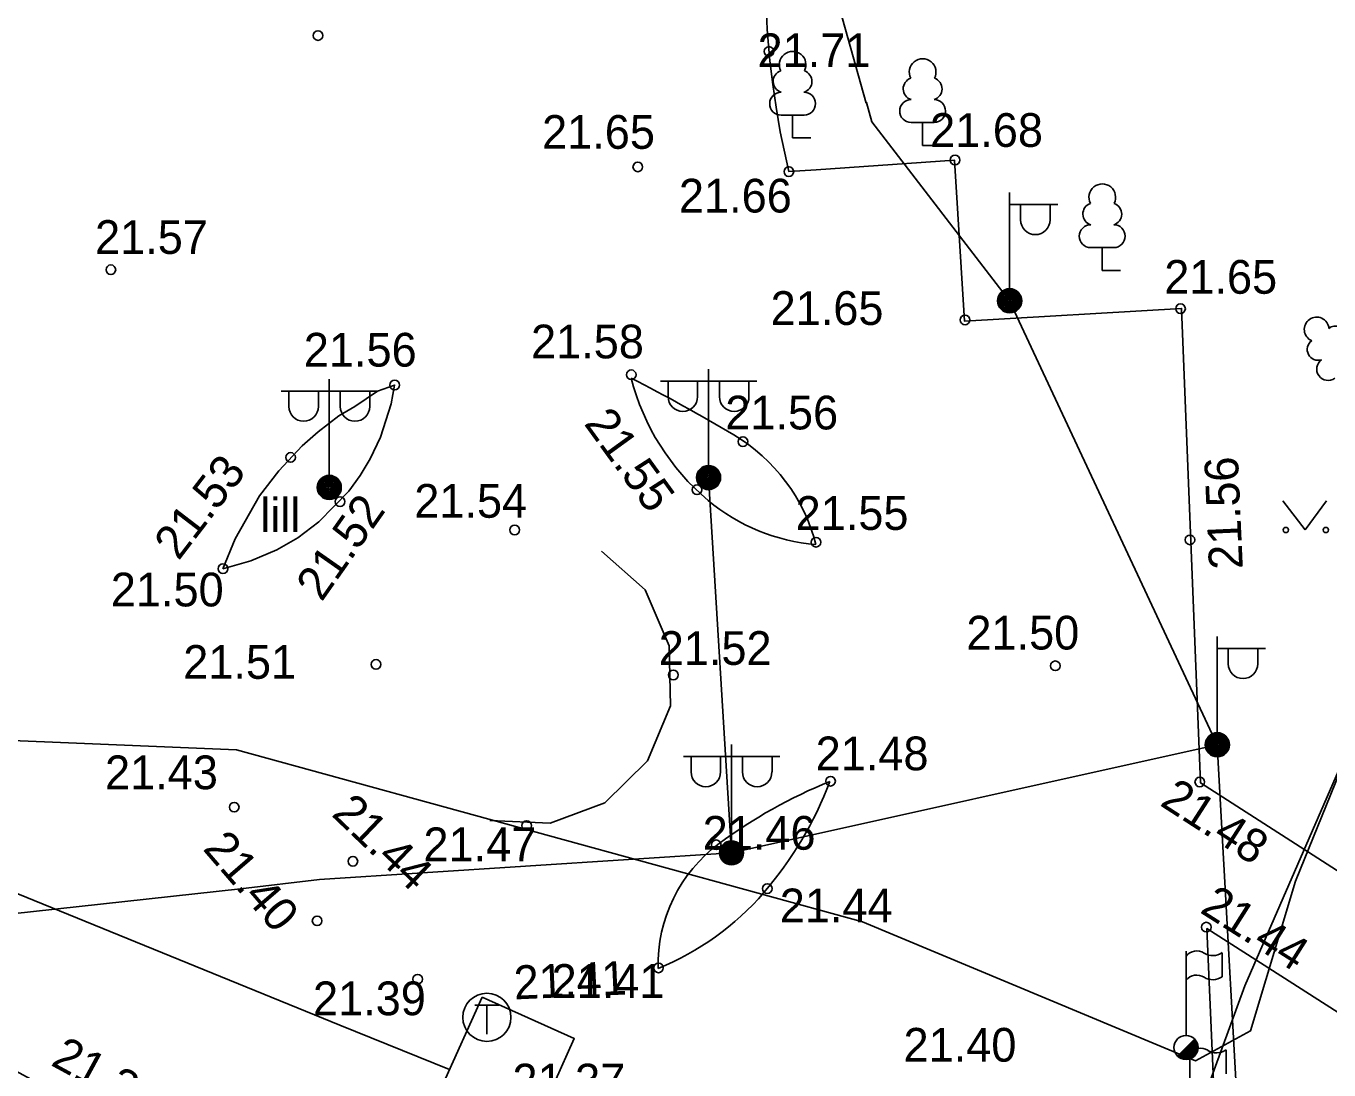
# Model space of a CAD drawing. Extents: x 714038 to 714279, y 6589845 to 6590041.
# Drawn here: x 714222.12 to 714249.16, y 6589934.18 to 6589955.84 of the extents above; entities that cross this region are included whole.
import ezdxf

# ---------------------------------------------------------------- set-up
doc = ezdxf.new("R2010")
doc.units = 0
for name, color, linetype in [('HALJASTUS', 7, 'Continuous'), ('KORGUS', 7, 'Continuous'), ('KPKAABEL', 7, 'Continuous'), ('MPKAABEL', 7, 'Continuous'), ('POST', 7, 'Continuous'), ('PUU', 7, 'Continuous'), ('RAJATIS', 7, 'Continuous'), ('TEE', 7, 'Continuous'), ('TKAEV', 7, 'Continuous'), ('TTRASS', 7, 'Continuous'), ('VTRASS', 7, 'Continuous')]:
    doc.layers.add(name, color=color, linetype=linetype)

msp = doc.modelspace()

# ---------------------------------------------------------------- linework, layer by layer
at = {"layer": 'HALJASTUS'}
for p, q in [((714248.205, 6589945.991), (714248.668, 6589945.384)), ((714248.668, 6589945.384), (714249.114, 6589945.991))]:
    msp.add_line(p, q, dxfattribs=at)
for centre in [(714248.267, 6589945.384), (714249.096, 6589945.384)]:
    msp.add_circle(centre, 0.055, dxfattribs=at)
at = {"layer": 'KORGUS'}
for centre in [(714228.182, 6589955.646), (714237.541, 6589955.316), (714241.402, 6589953.063), (714234.818, 6589952.92), (714237.953, 6589952.822), (714223.882, 6589950.785), (714246.081, 6589949.977), (714241.609, 6589949.744), (714234.682, 6589948.606), (714229.772, 6589948.392), (714236.999, 6589947.218), (714227.612, 6589946.89), (714236.047, 6589946.219), (714228.639, 6589945.973), (714232.264, 6589945.384), (714246.276, 6589945.179), (714238.517, 6589945.13), (714226.209, 6589944.581), (714229.385, 6589942.594), (714243.482, 6589942.565), (714235.554, 6589942.375), (714238.818, 6589940.17), (714246.481, 6589940.154), (714226.442, 6589939.631), (714232.51, 6589939.249), (714236.445, 6589938.85), (714228.905, 6589938.508), (714237.504, 6589937.941), (714228.163, 6589937.272), (714246.616, 6589937.141), (714235.247, 6589936.296), (714230.248, 6589936.061)]:
    msp.add_circle(centre, 0.1, dxfattribs=at)
at = {"layer": 'KPKAABEL'}
msp.add_lwpolyline([(714278.95, 6590013.083), (714274.696, 6590002.154), (714268.806, 6589986.746), (714264.689, 6589977.209), (714260.118, 6589965.851), (714258.032, 6589961.24), (714253.05, 6589949.372), (714248.466, 6589938.096), (714247.531, 6589934.989), (714246.389, 6589934.367), (714239.483, 6589937.254), (714226.492, 6589940.819), (714222.669, 6589940.979), (714220.982, 6589941.049), (714220.257, 6589940.365), (714218.76, 6589936.611), (714215.836, 6589929.757), (714212.225, 6589922.206), (714208.098, 6589916.26), (714202.344, 6589907.69)], dxfattribs=at)
at = {"layer": 'MPKAABEL'}
for points in [[(714167.029, 6589999.261), (714167.805, 6589985.535), (714167.801, 6589985.524), (714168.701, 6589969.69), (714168.856, 6589964.517), (714181.003, 6589963.765), (714182.873, 6589963.649), (714187.834, 6589963.342), (714201.122, 6589963.986), (714214.138, 6589964.636), (714217.634, 6589964.759), (714217.843, 6589958.743), (714218.335, 6589947.958), (714218.782, 6589937.076), (714219.871, 6589937.206), (714226.57, 6589937.936), (714228.214, 6589938.132), (714236.763, 6589938.683), (714246.845, 6589940.926), (714247.938, 6589921.303)], [(714246.845, 6589940.926), (714242.535, 6589950.141), (714239.677, 6589953.853), (714239.565, 6589954.253), (714239.558, 6589954.244), (714238.036, 6589959.673), (714239.482, 6589959.737), (714240.828, 6589959.797), (714241.687, 6589959.835), (714251.347, 6589960.263), (714264.335, 6589960.615)], [(714236.763, 6589938.683), (714236.286, 6589946.472)]]:
    msp.add_lwpolyline(points, dxfattribs=at)
at = {"layer": 'POST'}
for p, q in [((714242.535, 6589950.391), (714242.535, 6589952.391)), ((714242.535, 6589952.141), (714243.535, 6589952.141)), ((714242.761, 6589951.82), (714242.761, 6589952.141)), ((714243.374, 6589951.82), (714243.374, 6589952.141)), ((714228.415, 6589946.517), (714228.415, 6589948.517)), ((714236.286, 6589946.722), (714236.286, 6589948.722)), ((714228.415, 6589948.267), (714227.415, 6589948.267)), ((714227.576, 6589947.946), (714227.576, 6589948.267)), ((714228.188, 6589947.946), (714228.188, 6589948.267)), ((714228.415, 6589948.267), (714229.415, 6589948.267)), ((714228.642, 6589947.946), (714228.642, 6589948.267)), ((714229.254, 6589947.946), (714229.254, 6589948.267)), ((714236.286, 6589948.472), (714235.286, 6589948.472)), ((714235.446, 6589948.151), (714235.446, 6589948.472)), ((714236.059, 6589948.151), (714236.059, 6589948.472)), ((714236.286, 6589948.472), (714237.286, 6589948.472)), ((714236.512, 6589948.151), (714236.512, 6589948.472)), ((714237.125, 6589948.151), (714237.125, 6589948.472)), ((714246.845, 6589941.176), (714246.845, 6589943.176)), ((714246.845, 6589942.926), (714247.845, 6589942.926)), ((714247.072, 6589942.605), (714247.072, 6589942.926)), ((714247.684, 6589942.605), (714247.684, 6589942.926)), ((714236.763, 6589940.683), (714235.763, 6589940.683)), ((714235.924, 6589940.362), (714235.924, 6589940.683)), ((714236.537, 6589940.362), (714236.537, 6589940.683)), ((714236.763, 6589938.933), (714236.763, 6589940.933)), ((714236.763, 6589940.683), (714237.763, 6589940.683)), ((714236.99, 6589940.362), (714236.99, 6589940.683)), ((714237.603, 6589940.362), (714237.603, 6589940.683)), ((714246.017, 6589934.466), (714246.371, 6589934.819))]:
    msp.add_line(p, q, dxfattribs=at)
for centre, radius in [((714242.535, 6589950.141), 0.25), ((714242.535, 6589950.141), 0.225), ((714242.535, 6589950.141), 0.2), ((714242.535, 6589950.141), 0.175), ((714242.535, 6589950.141), 0.15), ((714242.535, 6589950.141), 0.125), ((714242.535, 6589950.141), 0.1), ((714242.535, 6589950.141), 0.075), ((714242.535, 6589950.141), 0.05), ((714242.535, 6589950.141), 0.025), ((714236.286, 6589946.472), 0.25), ((714236.286, 6589946.472), 0.225), ((714236.286, 6589946.472), 0.2), ((714236.286, 6589946.472), 0.175), ((714236.286, 6589946.472), 0.15), ((714228.415, 6589946.267), 0.25), ((714228.415, 6589946.267), 0.225), ((714228.415, 6589946.267), 0.2), ((714228.415, 6589946.267), 0.175), ((714228.415, 6589946.267), 0.15), ((714228.415, 6589946.267), 0.125), ((714228.415, 6589946.267), 0.1), ((714236.286, 6589946.472), 0.125), ((714236.286, 6589946.472), 0.1), ((714236.286, 6589946.472), 0.075), ((714236.286, 6589946.472), 0.05), ((714236.286, 6589946.472), 0.025), ((714228.415, 6589946.267), 0.075), ((714228.415, 6589946.267), 0.05), ((714228.415, 6589946.267), 0.025), ((714246.845, 6589940.926), 0.25), ((714246.845, 6589940.926), 0.225), ((714246.845, 6589940.926), 0.2), ((714246.845, 6589940.926), 0.175), ((714246.845, 6589940.926), 0.15), ((714246.845, 6589940.926), 0.125), ((714246.845, 6589940.926), 0.1), ((714246.845, 6589940.926), 0.075), ((714246.845, 6589940.926), 0.05), ((714246.845, 6589940.926), 0.025), ((714236.763, 6589938.683), 0.25), ((714236.763, 6589938.683), 0.225), ((714236.763, 6589938.683), 0.2), ((714236.763, 6589938.683), 0.175), ((714236.763, 6589938.683), 0.15), ((714236.763, 6589938.683), 0.125), ((714236.763, 6589938.683), 0.1), ((714236.763, 6589938.683), 0.075), ((714236.763, 6589938.683), 0.05), ((714236.763, 6589938.683), 0.025), ((714246.195, 6589934.643), 0.25)]:
    msp.add_circle(centre, radius, dxfattribs=at)
for centre, radius, start, end in [((714243.068, 6589951.82), 0.306, 180, 0), ((714235.753, 6589948.151), 0.306, 180, 0), ((714236.819, 6589948.151), 0.306, 180, 0), ((714227.882, 6589947.946), 0.306, 180, 0), ((714228.948, 6589947.946), 0.306, 180, 0), ((714247.378, 6589942.605), 0.306, 180, 0), ((714236.23, 6589940.362), 0.306, 180, 0), ((714237.296, 6589940.362), 0.306, 180, 0), ((714246.195, 6589934.643), 0.225, 224.8541, 45.0356), ((714246.195, 6589934.643), 0.2, 224.8427, 45.047), ((714246.195, 6589934.643), 0.175, 224.8281, 45.0616), ((714246.195, 6589934.643), 0.15, 224.8087, 45.081), ((714246.195, 6589934.643), 0.125, 224.7814, 45.1083), ((714246.195, 6589934.643), 0.1, 224.7406, 45.1491), ((714246.195, 6589934.643), 0.075, 224.6725, 45.2172), ((714246.195, 6589934.643), 0.05, 224.5363, 45.3534), ((714246.195, 6589934.643), 0.025, 224.1278, 45.7619)]:
    msp.add_arc(centre, radius, start, end, dxfattribs=at)
at = {"layer": 'PUU'}
for p, q in [((714238.27, 6589953.995), (714237.79, 6589953.995)), ((714238.03, 6589953.52), (714238.03, 6589953.995)), ((714240.969, 6589953.842), (714240.489, 6589953.842)), ((714240.729, 6589953.367), (714240.729, 6589953.842)), ((714238.41, 6589953.52), (714238.03, 6589953.52)), ((714241.109, 6589953.367), (714240.729, 6589953.367)), ((714244.697, 6589951.244), (714244.217, 6589951.244)), ((714244.457, 6589950.769), (714244.457, 6589951.244)), ((714244.837, 6589950.769), (714244.457, 6589950.769))]:
    msp.add_line(p, q, dxfattribs=at)
for centre, radius, start, end in [((714238.03, 6589955.04), 0.277, 332.5799, 207.4201), ((714240.729, 6589954.887), 0.277, 332.5799, 207.4201), ((714237.86, 6589954.693), 0.233, 109.0217, 253.1415), ((714238.2, 6589954.693), 0.233, 286.8508, 70.9859), ((714240.559, 6589954.539), 0.233, 109.0217, 253.1415), ((714240.899, 6589954.539), 0.233, 286.8508, 70.9859), ((714237.793, 6589954.232), 0.238, 90.0016, 269.3953), ((714238.267, 6589954.232), 0.238, 270.6047, 89.9984), ((714240.492, 6589954.079), 0.238, 90.0016, 269.3953), ((714240.967, 6589954.079), 0.238, 270.6047, 89.9984), ((714244.457, 6589952.289), 0.277, 332.5799, 207.4201), ((714244.287, 6589951.942), 0.233, 109.0217, 253.1415), ((714244.627, 6589951.942), 0.233, 286.8508, 70.9859), ((714244.219, 6589951.482), 0.238, 90.0016, 269.3953), ((714244.694, 6589951.482), 0.238, 270.6047, 89.9984), ((714248.906, 6589949.547), 0.256, 125.5389, 246.5536), ((714248.906, 6589949.547), 0.256, 4.5218, 125.5364), ((714249.293, 6589949.415), 0.202, 65.2382, 130.7412), ((714248.935, 6589949.13), 0.224, 125.4667, 288.5349), ((714249.144, 6589948.725), 0.237, 125.5377, 305.5366)]:
    msp.add_arc(centre, radius, start, end, dxfattribs=at)
at = {"layer": 'RAJATIS'}
for p, q in [((714246.195, 6589934.893), (714246.195, 6589936.643)), ((714246.947, 6589936.611), (714246.947, 6589936.111)), ((714246.272, 6589932.875), (714246.272, 6589934.625)), ((714247.025, 6589934.594), (714247.025, 6589934.094))]:
    msp.add_line(p, q, dxfattribs=at)
msp.add_lwpolyline([(714231.588, 6589935.687), (714233.5, 6589934.828), (714232.68, 6589933.004), (714230.768, 6589933.863)], close=True, dxfattribs=at)
for centre, radius, start, end in [((714246.418, 6589936.358), 0.288, 57.8941, 140.7366), ((714246.752, 6589936.891), 0.341, 237.8941, 305.0219), ((714246.418, 6589935.858), 0.288, 57.8941, 140.7366), ((714246.752, 6589936.391), 0.341, 237.8941, 305.0219), ((714246.495, 6589934.341), 0.288, 57.8941, 140.7366), ((714246.829, 6589934.873), 0.341, 237.8941, 305.0219)]:
    msp.add_arc(centre, radius, start, end, dxfattribs=at)
at = {"layer": 'TEE'}
for points in [[(714237.479, 6589956.311), (714237.505, 6589955.772), (714237.56, 6589955.119), (714237.618, 6589954.629), (714237.686, 6589954.16), (714237.775, 6589953.648), (714237.953, 6589952.822), (714238.519, 6589952.862), (714241.392, 6589953.057), (714241.599, 6589949.716), (714246.102, 6589949.982), (714246.498, 6589940.136), (714265.073, 6589928.211), (714265.223, 6589928.249)], [(714226.209, 6589944.581), (714226.789, 6589944.743), (714227.327, 6589944.973), (714227.761, 6589945.224), (714228.2, 6589945.55), (714228.822, 6589946.187), (714229.059, 6589946.512), (714229.267, 6589946.859), (714229.481, 6589947.311), (714229.7, 6589948.001), (714229.772, 6589948.392), (714229.415, 6589948.267), (714228.948, 6589947.946), (714228.614, 6589947.753), (714228.181, 6589947.423), (714227.855, 6589947.134), (714227.366, 6589946.614), (714226.97, 6589946.092), (714226.46, 6589945.198), (714226.209, 6589944.581)], [(714231.747, 6589939.353), (714232.996, 6589939.298), (714234.136, 6589939.721), (714235.017, 6589940.593), (714235.496, 6589941.731), (714235.468, 6589942.983), (714234.971, 6589944.139), (714234.063, 6589944.942)], [(714217.759, 6589936.392), (714238.65, 6589925.109), (714247.372, 6589920.348), (714247.69, 6589919.978), (714264.11, 6589911.01), (714265.191, 6589911.398), (714265.199, 6589917.222), (714265.151, 6589925.259), (714246.63, 6589937.111), (714247.349, 6589920.604), (714247.372, 6589920.348)]]:
    msp.add_lwpolyline(points, dxfattribs=at)
for centre, radius, start, end in [((714239.446, 6589949.764), 4.922, 194.4344, 229.8941), ((714216.172, 6589912.587), 40.434, 59.3114, 62.7589), ((714234.908, 6589944.157), 3.723, 14.4344, 59.3114), ((714238.81, 6589949.009), 3.935, 229.8941, 265.6713), ((714242.672, 6589930.572), 10.342, 111.9661, 126.5935), ((714231.594, 6589942.886), 7.706, 319.2821, 339.3171), ((714238.377, 6589936.356), 3.139, 126.5935, 181.2754), ((714233.1, 6589941.589), 5.718, 291.9661, 319.2821)]:
    msp.add_arc(centre, radius, start, end, dxfattribs=at)
at = {"layer": 'TKAEV'}
for p, q in [((714231.436, 6589935.519), (714231.936, 6589935.519)), ((714231.686, 6589934.919), (714231.686, 6589935.519))]:
    msp.add_line(p, q, dxfattribs=at)
msp.add_circle((714231.686, 6589935.269), 0.5, dxfattribs=at)
at = {"layer": 'TTRASS'}
msp.add_lwpolyline([(714180.868, 6589954.471), (714194.81, 6589948.35), (714193.9, 6589946.38), (714197.33, 6589944.94), (714198.25, 6589947.03), (714199.797, 6589946.458), (714205.14, 6589944.481), (714213.47, 6589941.4), (714220.708, 6589938.334), (714228.631, 6589935.107), (714230.913, 6589934.185)], dxfattribs=at)
at = {"layer": 'VTRASS'}
msp.add_lwpolyline([(714234.193, 6589907.469), (714237.059, 6589913.816), (714240.349, 6589920.042), (714244.05, 6589926.694), (714247.419, 6589935.922), (714252.894, 6589948.5), (714258.093, 6589959.582), (714259.692, 6589963.065), (714262.845, 6589969.359)], dxfattribs=at)

# ---------------------------------------------------------------- texts
at = {"layer": 'HALJASTUS'}
msp.add_text('lill', height=0.7, dxfattribs=at).set_placement((714226.983, 6589945.345))
at = {"layer": 'KORGUS'}
for s, p in [(' 21.71', (714237.043, 6589954.99)), (' 21.65', (714232.571, 6589953.295)), (' 21.68', (714240.624, 6589953.335)), (' 21.66', (714235.411, 6589951.973)), (' 21.57', (714223.294, 6589951.114)), (' 21.65', (714245.484, 6589950.287)), (' 21.65', (714237.314, 6589949.64)), (' 21.58 ', (714232.342, 6589948.946)), (' 21.56', (714227.626, 6589948.775)), (' 21.56', (714236.373, 6589947.471)), (' 21.54', (714229.919, 6589945.638)), (' 21.55', (714237.833, 6589945.386)), (' 21.50', (714223.621, 6589943.798)), (' 21.50', (714241.377, 6589942.903)), (' 21.52', (714234.992, 6589942.584)), (' 21.51', (714225.124, 6589942.295)), (' 21.48 ', (714238.249, 6589940.397)), (' 21.43', (714223.501, 6589940.004)), (' 21.46', (714235.904, 6589938.748)), (' 21.47', (714230.109, 6589938.51)), (' 21.44 ', (714237.504, 6589937.241)), (' 21.41', (714232.769, 6589935.673)), (' 21.39', (714227.817, 6589935.313)), (' 21.40', (714240.073, 6589934.349)), (' 21.37', (714231.956, 6589933.606))]:
    msp.add_text(s, height=0.7, dxfattribs=at).set_placement(p)
for s, rotation, p in [(' 21.55', 305.9467, (714233.534, 6589947.801)), (' 21.53', 52.5303, (714225.128, 6589944.525)), (' 21.56', 92.5441, (714247.387, 6589944.32)), (' 21.52', 54.9649, (714228.107, 6589943.663)), (' 21.48', 327.1839, (714245.412, 6589939.822)), (' 21.44', 316.2876, (714228.254, 6589939.647)), (' 21.40', 310.7677, (714225.604, 6589938.956)), (' 21.44', 327.6502, (714246.241, 6589937.597)), ('21.41', 2.5582, (714232.26, 6589935.64)), (' 21.35', 331.4612, (714222.384, 6589934.411))]:
    msp.add_text(s, height=0.7, rotation=rotation, dxfattribs=at).set_placement(p)

doc.saveas('drawing.dxf')
